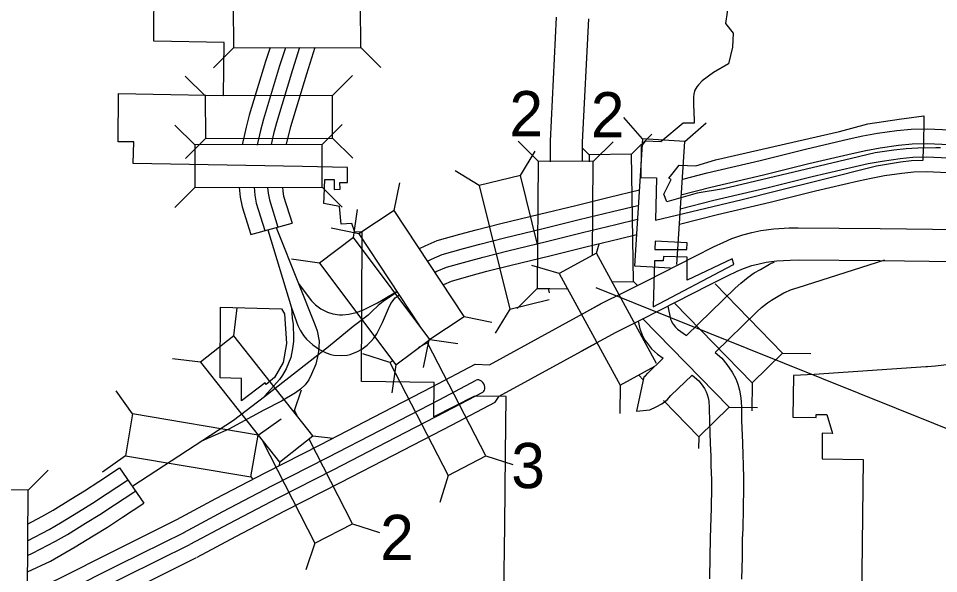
# Model space of a CAD drawing. Extents: x 535214 to 694517, y 381272 to 484355.
# Drawn here: x 552787 to 557082, y 463649 to 466241 of the extents above; entities that cross this region are included whole.
import ezdxf

# ---------------------------------------------------------------- set-up
doc = ezdxf.new("R2010")
doc.units = 0
for name, color, linetype in [('Level 10', 7, 'Continuous'), ('Level 15', 7, 'Continuous'), ('Level 19', 7, 'Continuous'), ('Level 20', 7, 'Continuous'), ('Level 22', 7, 'Continuous'), ('Level 6', 7, 'Continuous')]:
    doc.layers.add(name, color=color, linetype=linetype)

msp = doc.modelspace()

# ---------------------------------------------------------------- linework, layer by layer
at = {"layer": 'Level 10'}
for points in [[(555817.7, 464897.9), (555830.4, 464837.1), (555834.8, 464826.8), (555838.3, 464819.6), (555843.5, 464813.1), (555853.9, 464798.5), (555862.9, 464790.5), (555905.2, 464760.5)], [(555679.1, 464827.6), (555686.6, 464791.9), (555698.5, 464764), (555710.8, 464739.2), (555723.3, 464723.3), (555741.5, 464697.7), (555769.3, 464673), (555796, 464654)], [(556038.6, 464681.1), (556070.4, 464653.9), (556093.9, 464625.7), (556118.5, 464589.4), (556134.6, 464558.5), (556144, 464533), (556153, 464504.6), (556158.6, 464469.7), (556160.9, 464428.1), (556162.3, 464361.7), (556166, 464261.4), (556168.1, 464200.7), (556168.8, 464159.7), (556171.5, 464090.3)], [(555930.7, 464575.9), (555963.3, 464548.1), (555973.9, 464535.4), (555989.5, 464512.4), (555997.2, 464497.7), (556002, 464484.4), (556006.6, 464469.9), (556009.2, 464453.7), (556011, 464422.4), (556012.3, 464357.4), (556016.1, 464256.1), (556018.1, 464196.9), (556018.8, 464155.5), (556021.6, 464084.5)], [(556021.5, 464087.1), (556021.7, 464052.5), (556020.1, 463954.9), (556017.7, 463864.3)], [(556171.5, 464087.7), (556171.7, 464051.6), (556170.1, 463951.7), (556167.6, 463860.3)], [(556017.7, 463865.5), (556015.4, 463811.5), (556014.5, 463728.7), (556012, 463624.6)], [(556167.6, 463859.1), (556165.3, 463807.5), (556164.5, 463726.1), (556162, 463623.5)]]:
    msp.add_lwpolyline(points, dxfattribs=at)
at = {"layer": 'Level 15'}
for points in [[(555297.4, 466246.6), (555268.9, 465666.8), (555268.6, 465571.1)], [(555447.2, 466239.2), (555418.8, 465662.9), (555418.6, 465574.3)], [(555414.7, 464858.4), (555507.5, 464909), (555617.3, 464964.4), (555719.1, 465016.2), (555862.7, 465088.8), (555944.8, 465130.4), (556031.2, 465174.1), (556078.9, 465196.7), (556115.8, 465213.2), (556167.6, 465230.6), (556209.7, 465241.5), (556251.5, 465250.2), (556312.2, 465258.4), (556383.7, 465262.7), (556426.2, 465263), (556808.7, 465259.9), (558396.4, 465239)], [(555413.4, 464686.8), (555577.2, 464776.2), (555685, 464830.5), (555786.9, 464882.4), (555930.5, 464955), (556012.5, 464996.6), (556097.1, 465039.3), (556141.8, 465060.5), (556170.5, 465073.4), (556210.3, 465086.7), (556243.8, 465095.4), (556276.8, 465102.3), (556326.7, 465109), (556388.8, 465112.7), (556426.2, 465113), (556807.1, 465109.9), (558421.3, 465088.6), (558449.6, 465093.4)], [(555905.2, 464760.5), (556131.9, 464981.7), (556158.8, 465005.2), (556193.3, 465033), (556221.4, 465052.6), (556250.3, 465069.2), (556292.4, 465093.8), (556315.6, 465103.7)], [(556038.6, 464681.1), (556233.6, 464871.4), (556255.3, 464890.3), (556283.3, 464912.9), (556301.8, 464925.8), (556325.6, 464939.5), (556359.9, 464959.5), (556394.8, 464974.4), (556425.8, 464985), (556830.5, 465113.4)], [(554985.1, 464624.1), (555504.7, 464907.5)], [(555030.2, 464477.8), (555483.6, 464725.2)], [(553526.6, 463901.2), (553708.7, 463999), (553938.7, 464119.2), (554198.8, 464251.9), (554445, 464379.2), (554718.4, 464520.6), (554919.2, 464626.7), (554985.1, 464624.1)], [(555706.3, 464567.1), (555713.6, 464572.7), (555725.3, 464585), (555796, 464654)], [(553559.1, 463840.7), (553740.9, 463938.2), (553970.2, 464058.1), (554230.2, 464190.7), (554476.6, 464318.1), (554750.2, 464459.7), (554924.1, 464551.5)], [(555706.3, 464567.1), (555672.1, 464407.1), (555734.3, 464413.4), (555764.2, 464427.3), (555789.7, 464442.1), (555814.1, 464460.7), (555832.1, 464479.6), (555930.7, 464575.9)], [(553588.7, 463785.6), (553770.1, 463883), (553998.9, 464002.6), (554258.7, 464135.1), (554505.3, 464262.6), (554779.2, 464404.3), (554954.3, 464496)], [(553621.2, 463725), (553802.3, 463822.2), (554030.4, 463941.5), (554290.1, 464074), (554536.9, 464201.5), (554811, 464343.4), (555012.6, 464449.8), (555030.2, 464477.8)], [(548562.9, 461621.7), (548645.1, 461654.2), (548810.9, 461725.9), (549316.1, 461954.3), (549999.3, 462258.7), (550500.7, 462484.6), (550868, 462651.2), (551274.6, 462835.7), (551650, 463001.7), (551926.9, 463130.7), (552279.7, 463296.2), (552622.9, 463457.5), (552976.7, 463626.4), (553227, 463752.4), (553529.4, 463902.7)], [(548132.1, 461237), (548230.4, 461317.2), (548372.8, 461434.8), (548448.5, 461491), (548517.7, 461530), (548671.4, 461590.6), (548838.8, 461663), (549344.2, 461891.6), (550027.4, 462195.9), (550529, 462422), (550896.4, 462588.6), (551302.7, 462773), (551678.5, 462939.1), (551956, 463068.4), (552309, 463233.9), (552652.4, 463395.4), (553006.9, 463564.7), (553257.7, 463690.9), (553560, 463841.1)], [(548174.7, 461191.1), (548270.1, 461268.9), (548411.4, 461385.6), (548482.6, 461438.5), (548544.6, 461473.4), (548695.3, 461532.9), (548864, 461605.9), (549369.8, 461834.5), (550053, 462138.9), (550554.7, 462365), (550922.2, 462531.6), (551328.3, 462716), (551704.3, 462882.2), (551982.5, 463011.8), (552335.5, 463177.4), (552679.1, 463338.9), (553034.4, 463508.6), (553285.7, 463635), (553587.8, 463785.1)], [(548192.5, 461116.8), (548313.7, 461215.8), (548453.8, 461331.4), (548520.1, 461380.7), (548574.2, 461411.2), (548721.5, 461469.3), (548891.8, 461543), (549398, 461771.8), (550081.1, 462076.2), (550583.1, 462302.4), (550950.6, 462469), (551356.4, 462653.2), (551732.7, 462819.6), (552011.6, 462949.5), (552364.7, 463115.1), (552708.6, 463276.7), (553064.7, 463446.9), (553316.4, 463573.5), (553618.4, 463723.6)]]:
    msp.add_lwpolyline(points, dxfattribs=at)
msp.add_ellipse((554939.2, 464523.8), major_axis=(15.1, -27.7), ratio=0.696636, start_param=0, end_param=3.141593, dxfattribs=at)
at = {"layer": 'Level 19'}
for points in [[(553961.2, 466104.7), (553940.6, 466040), (553864.5, 465789.4), (553849.9, 465733.1), (553834.3, 465664.7), (553831.6, 465649.9)], [(554032.9, 466103.3), (554006.2, 466019.6), (553930.7, 465770.8), (553916.7, 465716.9), (553901.7, 465650.7), (553901.4, 465649.1)], [(554099, 466104.9), (554065.9, 466001), (553990.9, 465753.8), (553977.4, 465702.1), (553966.1, 465652.4)], [(554171, 466104.6), (554131.6, 465980.6), (554057.1, 465735.1), (554044.2, 465685.8), (554036.8, 465653)], [(555888.4, 465490.5), (556001.9, 465519.7), (556248.8, 465577.2), (556460.3, 465629.8), (556663.4, 465677.7), (556727.7, 465691.7), (556797, 465704.3), (556885.9, 465717.1), (556953.3, 465723.6), (557028.3, 465725.8), (557135.1, 465720.8), (557282, 465707.6), (557377.6, 465697.1), (557515.3, 465678.5), (557785.5, 465644.2), (558123.8, 465602), (558207.7, 465594.2), (558297.3, 465594), (558365.8, 465598.1), (558485.1, 465615.4), (558542.2, 465628.6)], [(555878.4, 465416.9), (556018.3, 465452.9), (556264.9, 465510.3), (556476.5, 465562.9), (556678.6, 465610.6), (556741.2, 465624.3), (556808.1, 465636.5), (556894.1, 465648.8), (556957.7, 465654.9), (557027.7, 465657), (557130.4, 465652.2), (557275.2, 465639.2), (557369.2, 465628.9), (557506.3, 465610.4), (557776.9, 465575.9), (558116.4, 465533.6), (558204.4, 465525.5), (558299.3, 465525.2), (558372.8, 465529.7), (558497.8, 465547.8), (558571.1, 465564.7)], [(555874.8, 465351.4), (556033.2, 465392.2), (556279.6, 465449.5), (556491.2, 465502.2), (556692.5, 465549.7), (556753.5, 465563), (556818.1, 465574.8), (556901.5, 465586.7), (556961.6, 465592.5), (557027.2, 465594.5), (557126.1, 465589.8), (557269, 465577), (557361.6, 465566.8), (557498.2, 465548.4), (557769, 465513.9), (558109.7, 465471.5), (558201.4, 465463), (558301.1, 465462.7), (558379.2, 465467.4), (558509.3, 465486.3), (558589.7, 465504.9)], [(555873.1, 465280), (556049.5, 465325.4), (556295.7, 465382.7), (556507.4, 465435.4), (556707.7, 465482.6), (556767, 465495.5), (556829.2, 465506.9), (556909.7, 465518.5), (556965.9, 465523.9), (557026.6, 465525.7), (557121.5, 465521.2), (557262.1, 465508.6), (557353.3, 465498.6), (557489.3, 465480.2), (557760.5, 465445.7), (558102.2, 465403.1), (558198.2, 465394.2), (558303.1, 465394), (558386.2, 465399), (558522, 465418.7), (558615.7, 465440.3)], [(553817.9, 465452.8), (553822.1, 465406.3), (553830.6, 465361.5), (553871.3, 465231.4)], [(553886.9, 465453.3), (553890.2, 465415.8), (553897.4, 465378.2), (553937.5, 465249.9)], [(553949.8, 465451.3), (553952.2, 465424.4), (553958.1, 465393.4), (553997.8, 465266.8)], [(554018.8, 465452.1), (554020.4, 465433.9), (554024.9, 465410.1), (554064, 465285.3)], [(554658.7, 465166.4), (554685.8, 465179.5), (554741.5, 465203.3), (554846.5, 465233), (554923.1, 465253.5), (555039.1, 465282.6), (555219.7, 465327.1), (555388.1, 465367.9), (555543.6, 465406.2), (555685.8, 465440)], [(554698.8, 465109.5), (554714.3, 465116.9), (554764.5, 465138.4), (554864.7, 465166.7), (554940.3, 465186.9), (555055.7, 465215.9), (555236, 465260.3), (555404.4, 465301.1), (555559.8, 465339.3), (555678.5, 465367.6)], [(553871.3, 465231.4), (554064, 465285.3)], [(554731.5, 465055.9), (554740.1, 465060), (554785.4, 465079.3), (554881.3, 465106.5), (554956, 465126.4), (555070.7, 465155.2), (555250.9, 465199.6), (555419.2, 465240.4), (555574.5, 465278.6), (555676.2, 465302.8)], [(553951.8, 465253.9), (554061.1, 464889.3), (554090.8, 464806.5), (554101.8, 464785.4), (554117.3, 464761.1), (554131.3, 464742.6), (554160.5, 464716), (554192.2, 464694.3), (554223.5, 464679), (554244.7, 464671.2), (554259.4, 464668.9), (554293.2, 464666.9), (554321.9, 464668.7), (554335.9, 464671.6), (554370.2, 464685.1), (554390.4, 464696.2), (554414.9, 464715.4), (554433.4, 464733.2), (554445.4, 464747.9), (554459.7, 464768.2), (554486.2, 464821.5), (554514.2, 464887.1), (554525.7, 464909.4), (554545.9, 464935.4), (554554.7, 464943.1), (554564, 464950.9)], [(553989.3, 465264.4), (554094.6, 465003.7), (554116.1, 464973.7), (554155.5, 464922.1), (554173.3, 464903.8), (554198, 464885.3), (554229.3, 464869.5), (554255.2, 464861.9), (554285.5, 464857.4), (554299.7, 464857.4), (554329.5, 464859.9), (554363, 464867.1), (554395, 464878.6), (554462.2, 464912.2), (554489.2, 464927.7), (554555, 464966.7)], [(554771.7, 464998.7), (554808.3, 465014.3), (554899.5, 465040.2), (554973.3, 465059.9), (555087.3, 465088.5), (555267.2, 465132.8), (555435.5, 465173.6), (555590.6, 465211.8), (555673.6, 465231.5)], [(554094.6, 465003.7), (554171, 464811.4), (554180.7, 464781.9), (554190, 464734.3), (554189, 464705.3), (554185.7, 464675.2), (554174.5, 464625.9), (554155, 464579.1), (554142, 464553.1), (554124.7, 464530.8), (554104, 464509.1), (554080, 464492), (554014.2, 464453.3), (553932.5, 464412.3), (553769.3, 464323), (553642, 464266.5)], [(554556.2, 464965.2), (554546.7, 464958.7), (554489.4, 464918.6), (554466.4, 464900.1), (554435.7, 464872.4), (554418.9, 464855.3), (554349.2, 464802.6), (554233.5, 464707), (553935.5, 464474.3), (553790.3, 464364), (553320.7, 464056.8)], [(554061.1, 464889.3), (554065, 464841), (554069, 464811.5), (554070.5, 464749.4), (554070.8, 464732.6), (554066.8, 464699.3), (554059, 464657.5), (554036, 464604.7), (554019.7, 464575.7), (554006.2, 464555.2), (553937.3, 464478.6)], [(552830.2, 463880.1), (552896.8, 463914.7), (552948.7, 463944.7), (553031.3, 463995.8), (553096, 464035), (553163, 464079.5), (553259.5, 464142.9)], [(553259.5, 464142.9), (553372.3, 463977.7)], [(552829.2, 463802.1), (552929.9, 463854.4), (552984, 463885.7), (553067.2, 463937.2), (553132.8, 463976.9), (553200.8, 464022.1), (553292.1, 464082), (553299.1, 464086.3)], [(552829.4, 463733.2), (552852.3, 463743.7), (552960, 463799.6), (553016.1, 463832.1), (553099.8, 463883.9), (553166.3, 463924.1), (553235.3, 463969.9), (553325.7, 464029.3), (553334.7, 464034.9)], [(552937.2, 463707), (553051.4, 463773.1), (553135.7, 463825.2), (553203.1, 463866.1), (553273.2, 463912.6), (553372.3, 463977.7)], [(552830, 463657.8), (552937.2, 463707)]]:
    msp.add_lwpolyline(points, dxfattribs=at)
at = {"layer": 'Level 20'}
for p, q in [((553790.5, 466103.7), (553697.4, 466010.1)), ((554384.5, 466105.2), (554478.1, 466012.1)), ((553659, 465878.5), (553565.5, 465971.6)), ((554253, 465880), (554346.1, 465973.6)), ((553610.2, 465649.7), (553516.6, 465742.8)), ((554204.2, 465651.2), (554297.3, 465744.8)), ((555699.5, 465679), (555612.2, 465778.1)), ((555897.1, 465666.5), (555996.1, 465753.7)), ((555648.5, 465606.8), (555742.5, 465699.5)), ((553659.6, 465680.5), (553566.5, 465586.9)), ((554253.6, 465682), (554347.1, 465588.9)), ((555212.7, 465573.7), (555120, 465667.6)), ((555469.5, 465572), (555563.4, 465664.8)), ((555699.5, 465679), (555661.9, 465086.2)), ((555897.1, 465666.5), (555699.5, 465679)), ((555860.6, 465091.6), (555897.1, 465666.5)), ((555130.1, 465507.8), (555198.4, 465620.7)), ((555450.5, 465603.9), (555419.2, 465634.4)), ((555212.7, 465573.7), (555208.8, 464979.7)), ((555469.5, 465572), (555212.7, 465573.7)), ((555648.5, 465606.8), (555450.5, 465603.9)), ((555450.5, 465603.9), (555451, 465571.5)), ((555466.6, 465133.9), (555469.5, 465572)), ((555657, 465012.8), (555648.5, 465606.8)), ((554937.8, 465460.4), (554824.9, 465528.7)), ((555130.1, 465507.8), (554937.8, 465460.4)), ((555210.9, 465179.6), (555130.1, 465507.8)), ((553610.7, 465451.7), (553517.6, 465358.1)), ((554204.7, 465453.2), (554298.3, 465360.1)), ((554540.7, 465344.4), (554567.3, 465473.7)), ((554937.8, 465460.4), (555079.9, 464883.6)), ((554350.8, 465217.2), (554369.6, 465347.8)), ((554540.7, 465344.4), (554375.4, 465235.5)), ((554867.6, 464848.4), (554540.7, 465344.4)), ((554375.4, 465235.5), (554246.1, 465262.1)), ((554375.4, 465235.5), (554658.8, 464805.4)), ((554350.8, 465217.2), (554192.3, 465098.5)), ((554706.8, 464741.6), (554350.8, 465217.2)), ((555484.4, 465144.1), (555497.5, 465188.8)), ((555484.4, 465144.1), (555310.6, 465049.3)), ((555764.9, 464629.9), (555484.4, 465144.1)), ((554192.3, 465098.5), (554061.7, 465117.3)), ((554192.3, 465098.5), (554548.3, 464623)), ((555310.6, 465049.3), (555183.9, 465086.5)), ((555661.9, 465086.2), (555830.5, 465075.5)), ((555310.6, 465049.3), (555595, 464527.8)), ((555556.7, 465011.4), (555657, 465012.8)), ((555657, 465012.8), (555674.6, 464995.7)), ((555208.8, 464979.7), (555114.9, 464887)), ((555208.8, 464979.7), (555267.3, 464979.3)), ((555265.2, 464959.2), (555260.2, 464979.2)), ((555267.3, 464979.3), (555346.7, 464978.8)), ((556353.6, 464678.3), (556038.1, 465001.8)), ((555079.9, 464883.6), (555264.1, 464929)), ((553792.9, 464758.4), (553808.4, 464889.5)), ((555079.9, 464883.6), (555011.5, 464770.7)), ((555850.7, 464910.3), (556211.9, 464540.1)), ((554702.3, 464739.5), (554867.6, 464848.4)), ((554867.6, 464848.4), (554996.9, 464821.9)), ((556104, 464426.1), (555699.9, 464840.3)), ((553792.9, 464758.4), (553637.5, 464635.8)), ((554160.9, 464292.1), (553792.9, 464758.4)), ((554548.3, 464623), (554706.8, 464741.6)), ((554696.2, 464725.8), (554653.8, 464703.8)), ((554702.3, 464739.5), (554675.7, 464610.2)), ((554969.1, 464198.2), (554696.2, 464725.8)), ((554706.8, 464741.6), (554837.4, 464722.8)), ((554520.3, 464634.8), (554394.6, 464674.8)), ((556211.9, 464540.1), (556353.6, 464678.3)), ((556353.6, 464678.3), (556485.6, 464676.7)), ((553637.5, 464635.8), (553506.4, 464651.2)), ((553637.5, 464635.8), (554005.5, 464169.5)), ((554535.1, 464642.5), (554520.3, 464634.8)), ((554520.3, 464634.8), (554793.3, 464107.2)), ((554548.3, 464623), (554529.5, 464492.3)), ((555595, 464527.8), (555757.6, 464616.5)), ((555681.9, 464575.2), (555703.2, 464553.4)), ((556211.9, 464540.1), (556210.3, 464408.1)), ((553319.7, 464394.3), (553243.2, 464501.9)), ((554076.2, 464410.4), (554107.7, 464507.3)), ((555595, 464527.8), (555593.4, 464395.8)), ((555797.4, 464456.9), (555962.3, 464287.9)), ((554076.2, 464410.4), (554068.9, 464406.7)), ((554087.9, 464387.4), (554076.2, 464410.4)), ((555962.3, 464287.9), (556104, 464426.1)), ((556104, 464426.1), (556236, 464424.5)), ((553319.7, 464394.3), (553286.8, 464199.1)), ((553905.4, 464295.5), (553319.7, 464394.3)), ((553905.4, 464295.5), (554013, 464372)), ((553872.5, 464100.3), (553905.4, 464295.5)), ((554005.5, 464169.5), (554160.9, 464292.1)), ((554160.9, 464292.1), (554255.5, 464281)), ((555962.3, 464287.9), (555961.6, 464232.9)), ((553926.3, 464268.5), (554169.7, 463791.3)), ((554346.1, 463881.2), (554144.2, 464277)), ((553286.8, 464199.1), (553179.2, 464122.6)), ((553286.8, 464199.1), (553872.5, 464100.3)), ((554793.3, 464107.2), (554969.1, 464198.2)), ((554969.1, 464198.2), (555094.9, 464158.2)), ((554005.5, 464169.5), (554003.5, 464152.7)), ((552832.3, 464039), (552926.1, 464131.8)), ((553872.5, 464100.3), (553879.5, 464090.5)), ((554793.3, 464107.2), (554753.3, 463981.4)), ((552832.3, 464039), (552634.3, 464040.1)), ((552829.6, 463557.9), (552832.3, 464039)), ((554169.7, 463791.3), (554346.1, 463881.2)), ((554346.1, 463881.2), (554471.6, 463840.5)), ((554169.7, 463791.3), (554128.9, 463665.7))]:
    msp.add_line(p, q, dxfattribs=at)
for points in [[(553790.5, 466103.7), (554384.5, 466105.2), (554384, 466303.2), (553790, 466301.7)], [(553659.6, 465680.5), (554253.6, 465682), (554253, 465880), (553659, 465878.5)], [(553610.7, 465451.7), (554204.7, 465453.2), (554204.2, 465651.2), (553610.2, 465649.7)]]:
    msp.add_lwpolyline(points, close=True, dxfattribs=at)
at = {"layer": 'Level 22'}
msp.add_lwpolyline([(555481.4, 464984.7), (557762.5, 464067.9)], dxfattribs=at)
at = {"layer": 'Level 6'}
for points in [[(555064, 464476), (554915.8, 464477.8), (554725.4, 464380.5), (554727, 464541.2), (554389, 464545.3), (554392, 465244.7), (554357, 465242.9), (554343.1, 465283.4), (554293.4, 465280.8), (554286.2, 465363.1), (554213, 465376), (554213.5, 465405.7), (554213.5, 465409.5), (554216.6, 465489.1), (554260.3, 465488.6), (554260.3, 465442.5), (554288.6, 465443.6), (554287.4, 465474.2), (554322.2, 465474.6), (554322.2, 465544.7), (554112.7, 465549.6), (553496.1, 465559.5), (553323.3, 465562.8), (553325.7, 465663.7), (553252.8, 465664.4), (553254.1, 465890.6), (553415.7, 465887.2), (553743.9, 465880.3), (553747.4, 466128.1), (553418.3, 466134.6), (553419.2, 466217.1), (553423.9, 466554.2)], [(556103.3, 466322.7), (556087.5, 466216.3), (556122.1, 466171.9), (556119.3, 466107.1), (556100.9, 466028.5), (556031.5, 465987.9), (555978.7, 465948.7), (555960.5, 465930.7), (555953.4, 465920.8), (555948.3, 465912.8), (555944.3, 465905.8), (555942.1, 465900.7), (555939, 465886.5), (555938.1, 465874.9), (555937.9, 465839.6), (555937.7, 465826.8), (555939.2, 465815.6), (555940.4, 465751.3), (555889.4, 465751.3), (555785.8, 465664.6), (555711.5, 465667.1), (555693.2, 465641.9), (555691.3, 465498.5), (555765.7, 465496.4), (555760.6, 465298), (556164.8, 465395.6), (556331.2, 465437.3), (556525.5, 465485.3), (556791.7, 465552), (556904.5, 465571.8)], [(556904.5, 465571.8), (556954.8, 465577), (557009.6, 465579.6), (557010.5, 465636), (557068, 465638.5), (557091, 465638.1)], [(557408.8, 464657.8), (557067.6, 464617.9), (557030, 464613.9), (557022.3, 464613.4), (556500.5, 464578.4), (556404.5, 464573.5), (556400.7, 464378.9), (556510.2, 464377.1), (556510.6, 464391.4), (556559.5, 464391.8), (556586, 464303.6), (556537.5, 464304.1), (556537.7, 464184.6), (556729, 464181.6), (556721, 463523)], [(555053.2, 463544.6), (555056.6, 463875.5), (555060, 464206.3), (555064, 464476)]]:
    msp.add_lwpolyline(points, dxfattribs=at)
for points in [[(557010.5, 465636), (556930.3, 465631.2), (556872.6, 465625.1), (556785.9, 465612.9), (556675.2, 465586.5), (556077.3, 465444.8), (555954.4, 465425.3), (555812.5, 465384.8), (555798.7, 465420.4), (555833.7, 465489.2), (555823, 465494.9), (555830.8, 465504.4), (555843.1, 465520.1), (555870.2, 465556.1), (555949.3, 465552), (556039.9, 465579.7), (556618.8, 465713.3), (556750.7, 465748.7), (556897.7, 465770.3), (557012.8, 465786.2)], [(555907.1, 465161.1), (555908.5, 465193.6), (555758.1, 465200.7), (555757.1, 465162.3)], [(555750.2, 464893.8), (556120.8, 465090.8), (556125.3, 465093), (556117.5, 465118.3), (555908.2, 465018), (555907.4, 465126.4), (555796.9, 465129.3), (555796.7, 465108.9), (555755.8, 465109.4)], [(553827.6, 464456.1), (553828, 464559.7), (553729.1, 464562.4), (553730.5, 464892.2), (554015.3, 464884.9), (554029.6, 464861.2), (554037.9, 464723.1), (554022, 464634.8), (553981.8, 464563.6), (553943, 464532.1), (553937.9, 464539.2)]]:
    msp.add_lwpolyline(points, close=True, dxfattribs=at)

# ---------------------------------------------------------------- texts
at = {"layer": 'Level 20'}
for s, p in [('2', (555078.6, 465690.3)), ('2', (555458.4, 465685.2)), ('3', (555087.2, 464047.6)), ('2', (554475.3, 463712.1))]:
    msp.add_text(s, height=211.2, dxfattribs=at).set_placement(p)

doc.saveas('drawing.dxf')
